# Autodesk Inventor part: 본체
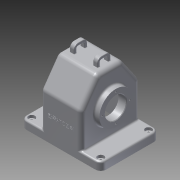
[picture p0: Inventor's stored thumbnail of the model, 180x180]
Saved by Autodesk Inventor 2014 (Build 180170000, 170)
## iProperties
Created: 2016-12
Part Number: 본체
Material: 알루미늄 6061
Document SubType Name: Modeling
Designer: USER
Density: 2.71 g/cm^3
Appearance: 알루미늄 - 평지
Mass: 1130.69 g
Surface Area: 1150.15 cm^2
Volume: 417.231 cm^3
Author: USER
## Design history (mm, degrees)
sketch "스케치1"
  geometry: L1 (75, -55)-(-75, -55); L2 (-75, -55)-(-75, 55); L3 (-75, 55)-(75, 55); L4 (75, 55)-(75, -55); L5 (75, -55)-(-75, 55); L6 (-75, -55)-(75, 55); 1 further point
  constraints: 12 end point, 2 midpoint, 2 parallel, 1 horizontal, 1 perpendicular
  dimensions: "d0" = 110 distance between parallel lines of L1 L3; "d1" = 150 distance between parallel lines of L2 L4
extrude "돌출1" new body sketch "스케치1" distance "d2" = 15; taper "d3" = 0 deg
sketch "스케치2"
  geometry: L1 (-55, 15)-(55, 15); L2 (55, 15)-(55, 80); L3 (55, 80)-(-55, 80); L4 (-55, 80)-(-55, 15); L5 (-55, 0)-(55, 0) reference; L6 (-55, 0)-(-55, 15) reference; L7 (55, 15)-(-55, 15) reference; L8 (55, 0)-(55, 15) reference; L9 (-55, 80)-(-23.491, 125); L10 (-23.491, 125)-(23.491, 125); L11 (23.491, 125)-(55, 80); 1 further point
  constraints: 14 end point, 2 parallel, 2 perpendicular, 1 horizontal
  dimensions: "d4" = 80 distance between parallel lines of L3 L5; "d5" = 35 deg angle of L4 L9; "d6" = 35 deg angle of L2 L11; "d7" = 125 distance from line of point (0, 0) L10
extrude "돌출2" join sketch "스케치2" stored distance "d8" = 77; taper "d9" = 0 deg
node "작업 평면1"
sketch "스케치3"
  geometry: L1 (-12.5, 125)-(12.5, 125); L2 (12.5, 125)-(12.5, 132); L3 (4.5, 140)-(-4.5, 140); L4 (-12.5, 132)-(-12.5, 125); L5 (-23.491, 125)-(23.491, 125) reference; L6 (-55, 0)-(55, 0) reference; A1 r 8 centre (4.5, 132) between (12.5, 132) and (4.5, 140); A2 r 8 centre (-4.5, 132) between (-4.5, 140) and (-12.5, 132); 2 further points
  constraints: 8 end point, 4 point on circle, 4 tangent, 2 centre point, 2 midpoint, 2 parallel, 1 equal radius, 1 horizontal, 1 perpendicular
  dimensions: "d11" = 25 distance between parallel lines of L4 L2; "d12" = 140 distance between parallel lines of L6 L3; "d13" = 8 radius of A1
extrude "돌출3" join sketch "스케치3" distance "d14" = 8; taper "d15" = 0 deg
sketch "스케치4"
  geometry: L1 (-125, 12.5)-(-125, -12.5) reference; L2 (-125, 12.5)-(-132, 12.5) reference; L3 (-140, 4.5)-(-140, -4.5) reference; L4 (-132, -12.5)-(-125, -12.5) reference; L5 (-132, 7.5)-(-130, 7.5); L6 (-130, 7.5)-(-130, -7.5); L7 (-130, -7.5)-(-132, -7.5); L8 (-135, -4.5)-(-135, 4.5); L9 (-130, -7.5)-(-125, -7.5); L10 (-125, -7.5)-(-125, 7.5); L11 (-125, 7.5)-(-130, 7.5); L12 (-130, 7.5)-(-130, -7.5); A1 r 8 centre (-132, 4.5) between (-132, 12.5) and (-140, 4.5) reference; A2 r 8 centre (-132, -4.5) between (-140, -4.5) and (-132, -12.5) reference; A3 r 3 centre (-132, 4.5) between (-132, 7.5) and (-135, 4.5); A4 r 3 centre (-132, -4.5) between (-135, -4.5) and (-132, -7.5); 1 further point
  constraints: 16 end point, 4 point on circle, 2 centre point, 2 parallel, 1 collinear, 1 horizontal, 1 perpendicular, 1 point on line, 5 other
  dimensions: "d16" = 15 distance between parallel lines of L7 L5
extrude "돌출4" cut sketch "스케치4" stored distance "d17" = 8; taper "d18" = 0 deg
sketch "스케치5"
  geometry: L1 (23.491, 125)-(55, 80) reference; L2 (55, 80)-(55, 15) reference; L3 (-55, 15)-(55, 15) reference; L4 (-55, 15)-(-55, 80) reference; L5 (-55, 80)-(-23.491, 125) reference; L6 (-23.491, 125)-(23.491, 125) reference; L7 (-55, 0)-(55, 0) reference; L8 (-55, 0)-(-55, 15) reference; L9 (55, 15)-(-55, 15) reference; L10 (55, 0)-(55, 15) reference; L11 (50, 78.424)-(20.888, 120); L12 (20.888, 120)-(-20.888, 120); L13 (-20.888, 120)-(-50, 78.424); L14 (-50, 78.424)-(-50, 20); L15 (-50, 20)-(50, 20); L16 (50, 20)-(50, 78.424); L17 (-50, 20)-(50, 20); L18 (50, 20)-(50, 0); L19 (50, 0)-(-50, 0); L20 (-50, 0)-(-50, 20); 1 further point
  constraints: 20 end point, 2 parallel, 1 collinear, 1 horizontal, 1 perpendicular, 1 point on line, 5 other
  dimensions: "d19" = 5 distance between parallel lines of L1 L11
extrude "돌출5" cut sketch "스케치5" stored distance "d20" = 67; taper "d21" = 0 deg
sketch "스케치6"
  geometry: L1 (33.5, 106)-(19.5, 92); L2 (19.5, 92)-(19.5, 65); L3 (19.5, 65)-(33.5, 65); L4 (38.5, 80)-(38.5, 15) reference; L5 (-33.5, 0)-(33.5, 0) reference; L6 (33.5, 106)-(33.5, 65); L7 (33.5, 120)-(33.5, 78.424) reference; 1 further point
  constraints: 8 end point, 2 perpendicular, 1 collinear, 1 vertical
  dimensions: "d22" = 54 diameter of L1.end L3; "d23" = 65 distance between parallel lines of L5 L3; "d24" = 45 deg angle of L1 L2; "d94" = 19 distance between parallel lines of L4 L2
revolve "회전1" sketch "스케치6" stored, may be unused: angle "d26" = 90 deg
sketch "스케치7"
  geometry: L1 (0, -55)-(0, 55) reference; C1 r 37.5 at (65, 0); 2 further points
  constraints: 1 centre point, 1 horizontal alignment, 1 midpoint
  dimensions: "d27" = 75 diameter of C1; "d28" = 65 distance from line of L1 C1.centre
extrude "돌출6" join sketch "스케치7" distance "d29" = 5; taper "d30" = 0 deg
sketch "스케치8"
  geometry: L1 (-15, 55)-(-15, -55) reference; L2 (0, 55)-(0, -55) reference; C1 r 31 at (-65, 0); 2 further points
  constraints: 1 centre point, 1 horizontal alignment, 1 midpoint
  dimensions: "d31" = 62 diameter of C1; "d32" = 65 distance from line of L2 C1.centre
extrude "돌출7" join sketch "스케치8" distance "d33" = 10; taper "d34" = 0 deg
hole "구멍1" diameter "d37" = 40; stored, may be unused: countersink angle "d41" = 90 deg, drill point angle "d43" = 118 deg; dims "d35" = 10, "d36" = 10, "d38" = 6, "d39" = 4, "d40" = 2, "d42" = 8
sketch "스케치9"
  geometry: C1 r 20 at (0, 0) reference; 2 further points
  constraints: 1 horizontal alignment
  dimensions: "d44" = 26 distance of C1.centre point (-26, 0)
hole "구멍2" sketch "스케치9" at (-26, 0) diameter "d45" = 2.459; stored, may be unused: countersink angle "d49" = 90 deg, drill point angle "d51" = 118 deg; dims "d46" = 6, "d47" = 4, "d48" = 2, "d50" = 8
sketch "스케치10"
  geometry: C1 r 20 at (0, 0) reference; 2 further points
  constraints: 1 horizontal alignment
  dimensions: "d55" = 29 distance of C1.centre point (29, 0)
hole "구멍3" sketch "스케치10" at (29, 0) diameter "d56" = 2.459; stored, may be unused: countersink angle "d60" = 90 deg, drill point angle "d62" = 118 deg; dims "d57" = 6, "d58" = 4, "d59" = 2, "d61" = 8
fillet "모깎기1" dims "d66" = 10
sketch "스케치11"
  geometry: A1 r 10 centre (-65, 45) between (-65, 55) and (-75, 45) reference; A2 r 10 centre (-65, -45) between (-75, -45) and (-65, -55) reference; 1 further point
hole "구멍4" sketch "스케치11" at (-65, -45), (-65, 45) diameter "d67" = 5; stored, may be unused: countersink angle "d71" = 90 deg, drill point angle "d73" = 118 deg; dims "d68" = 6, "d69" = 12, "d70" = 5, "d72" = 8
fillet "모깎기2" dims "d74" = 10
fillet "모깎기3" dims "d75" = 10
fillet "모깎기4" dims "d76" = 8
fillet "모깎기5" dims "d77" = 3
fillet "모깎기6" dims "d78" = 3
fillet "모깎기7" dims "d79" = 3
fillet "모깎기8" dims "d80" = 1
fillet "모깎기9" dims "d81" = 1
fillet "모깎기10" dims "d82" = 1
fillet "모깎기11" dims "d83" = 1
fillet "모깎기12" dims "d84" = 3
fillet "모깎기13" dims "d85" = 3
fillet "모깎기14" dims "d86" = 3
chamfer "모따기1" distance "d87" = 1; stored, may be unused: second distance "d88" = 2, angle "d89" = 45 deg
sketch "스케치12"
  geometry: L1 (130, 0)-(0, 0) reference; L2 (26.5, 76.847)-(26.5, 18) reference; 2 further points
  constraints: 1 other
  dimensions: "d90" = 38.5 distance from line of L2 point (65, 45); "d91" = 45 distance from line of point (65, 45) L1
feature "엠보싱1" sketch "스케치12" dims "d92" = 0.5, "d93" = 0
node "솔리드1"
mirror "대칭1"
pattern_circular "원형 패턴1" dims angle "d53" = 360 deg
pattern_circular "원형 패턴2" dims angle "d64" = 360 deg
mirror "대칭2"
node "투영된 루프1"
node "투영된 루프2"
node "투영된 루프3"
other parameters: "d10" = 18
